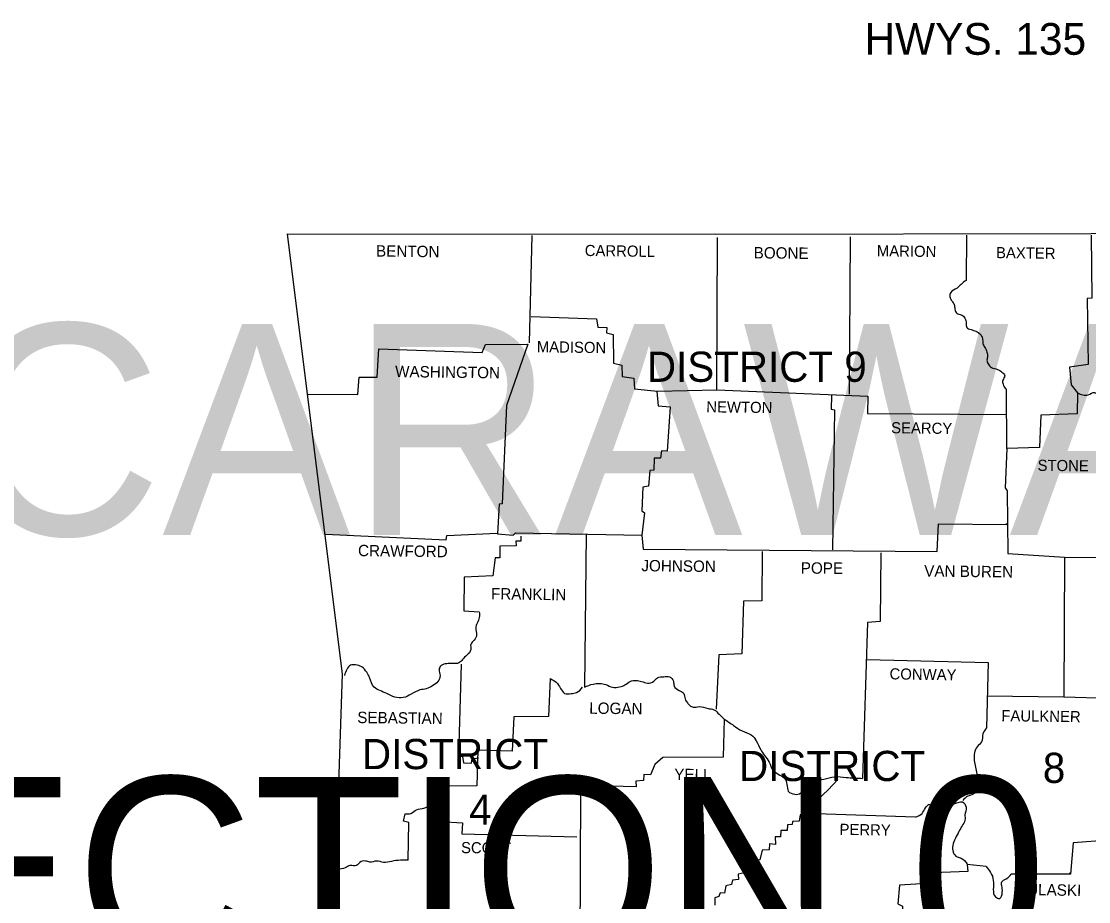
# Model space of a CAD drawing. Extents: x 166 to 3995, y -61 to 2074.
# Drawn here: x 2605.5 to 2999.8, y 1709.8 to 2035 of the extents above; entities that cross this region are included whole.
import ezdxf

# ---------------------------------------------------------------- set-up
doc = ezdxf.new("R2010")
doc.units = 0
for name, color, linetype in [('1', 7, 'Continuous'), ('2', 7, 'Continuous'), ('3', 7, 'Continuous'), ('R_Border', 7, 'Continuous')]:
    doc.layers.add(name, color=color, linetype=linetype)

msp = doc.modelspace()

# ---------------------------------------------------------------- linework, layer by layer
at = {"layer": '1'}
for points in [[(2703.71, 1956.42), (2861.92, 1956.32), (3000.75, 1956.61), (3164.54, 1959.16), (3240.46, 1960.92)], [(2703.71, 1956.42), (2723.96, 1793.81), (2715.15, 1528.37)], [(2794.01, 1955.83), (2793.13, 1916.21)], [(2954.67, 1956.03), (2954.47, 1939.3)], [(3000.75, 1956.03), (3000.95, 1932.74), (2999.28, 1932.64), (2999.58, 1908.28), (2992.73, 1907.3), (2993.32, 1900.75), (2995.66, 1897.71), (2995.47, 1889.98), (2982.16, 1889.5), (2981.67, 1877.56), (2969.54, 1877.17), (2968.95, 1862.69), (2969.64, 1861.51), (2969.93, 1838.42), (2990.87, 1837.05), (2990.58, 1785.49), (3007.21, 1785), (3007.21, 1732.56), (2994.1, 1731.58), (2993.12, 1720.04), (2971.11, 1719.94)], [(2793.82, 1925.89), (2817.89, 1925.11), (2818.47, 1921.98), (2821.8, 1921.88), (2821.7, 1919.92), (2824.05, 1919.34), (2824.25, 1908.67), (2827.28, 1907.99), (2827.48, 1903.78), (2831.78, 1903.19), (2831.98, 1899.28), (2840.49, 1898.4), (2862.4, 1898.89), (2862.6, 1955.15)], [(2911.62, 1955.34), (2911.33, 1897.22)], [(2711.44, 1897.22), (2729.73, 1897.13), (2730.22, 1903.58), (2736.97, 1903.58), (2737.56, 1914.05), (2775.72, 1912.68), (2776.89, 1915.62), (2792.64, 1915.72), (2784.72, 1893.02), (2783.15, 1856.72), (2781.98, 1856.62), (2781.39, 1845.66), (2787.17, 1845.17), (2788.05, 1846.05), (2834.72, 1845.17), (2835.21, 1839.99)], [(2840.29, 1898.2), (2840.68, 1892.92), (2845.18, 1892.63), (2844.01, 1876.19), (2841.96, 1876.29), (2841.56, 1873.65), (2839.22, 1873.65), (2839.12, 1869.14), (2837.65, 1869.05), (2837.16, 1863.27), (2835.01, 1862.98), (2834.72, 1854.17), (2835.69, 1853.49), (2834.72, 1845.17)], [(2862.4, 1898.89), (2918.17, 1896.54), (2918.08, 1890.18), (2969.25, 1889.79)], [(2904.77, 1896.83), (2904.67, 1891.75), (2905.94, 1891.45), (2905.16, 1839.79)], [(2969.54, 1877.17), (2969.44, 1899.18)], [(2835.21, 1839.99), (2943.81, 1839.11), (2944.3, 1849.38), (2969.54, 1849.09)], [(2969.25, 1849.19), (2969.54, 1849.48)], [(2717.89, 1845.56), (2762.41, 1843.51), (2762.61, 1845.08), (2781.2, 1845.96)], [(2814.17, 1845.56), (2813.48, 1789.11)], [(2790, 1844.78), (2790, 1843.02), (2788.14, 1843.02), (2788.24, 1841.26), (2782.27, 1841.16), (2782.18, 1836.76), (2780.51, 1836.76), (2779.63, 1830.2), (2769.06, 1829.71), (2768.97, 1817.29), (2774.64, 1816.9)], [(2879.14, 1839.21), (2879.04, 1820.91), (2872.29, 1820.81), (2871.7, 1801.34), (2863.09, 1801.05), (2862.11, 1780.89)], [(2922.97, 1838.72), (2922.77, 1813.28), (2918.08, 1812.89), (2916.22, 1755.36)], [(2990.87, 1837.05), (3041.16, 1836.76), (3045.46, 1838.81), (3045.17, 1800.56), (3042.24, 1799.29), (3039.59, 1797.04), (3038.71, 1796.16), (3038.62, 1785.2), (3006.62, 1785.2)], [(2917.88, 1799.29), (2962.59, 1798.21), (2962.01, 1774.04)], [(2767.99, 1797.53), (2767.01, 1763.87), (2768.48, 1763.48), (2768.77, 1761.13), (2771.71, 1760.93), (2772, 1762.6), (2774.35, 1762.99)], [(2800.86, 1792.24), (2800.18, 1778.25), (2787.46, 1778.15), (2786.77, 1765.43), (2774.15, 1765.73), (2773.76, 1752.62), (2760.55, 1752.52), (2760.16, 1739.41), (2768.48, 1738.92), (2768.18, 1734.91), (2810.65, 1733.73)], [(2962.1, 1785.88), (2990.58, 1785.49)], [(2865.14, 1777.27), (2864.75, 1763.18), (2842.45, 1763.09), (2839.51, 1760.54), (2837.85, 1756.63), (2835.4, 1756.82), (2835.3, 1754.57), (2832.47, 1754.28), (2832.56, 1752.22), (2818.38, 1752.62), (2817.89, 1751.05), (2812.02, 1750.86), (2811.82, 1693.62)], [(2907.12, 1754.96), (2903.6, 1751.15), (2899.78, 1747.53), (2895.38, 1746.84), (2895.38, 1742.25), (2893.22, 1741.95), (2892.83, 1739.6), (2890.39, 1739.41), (2890.19, 1738.33), (2888.53, 1738.23), (2888.43, 1736.18), (2886.08, 1736.08), (2885.89, 1733.73), (2883.93, 1733.73), (2884.03, 1730.99), (2881.88, 1731.19), (2881.78, 1729.04), (2879.14, 1728.84), (2878.35, 1725.32), (2875.03, 1725.03), (2874.73, 1723.07), (2872.97, 1722.58), (2872.48, 1720.52), (2870.23, 1720.04), (2870.43, 1717.98), (2868.18, 1717.78), (2867.79, 1716.22), (2865.73, 1715.63), (2865.24, 1712.99), (2863.68, 1713.09), (2863.19, 1711.72), (2861.72, 1711.23), (2861.62, 1708.59)], [(2748.32, 1725.22), (2748.62, 1739.02), (2746.66, 1739.6), (2747.25, 1742.25)], [(2935.79, 1741.07), (2895.47, 1742.34)], [(2961.91, 1722.77), (2954.86, 1723.56), (2955.16, 1720.92), (2942.34, 1720.43), (2941.95, 1716.61), (2929.91, 1715.93), (2929.23, 1709.08), (2930.99, 1708.2), (2930.99, 1703.7)], [(2992.63, 1720.13), (2993.12, 1720.62)]]:
    msp.add_lwpolyline(points, dxfattribs=at)
for points in [[(2954.47, 1939.3), (2952.71, 1937.83), (2951.15, 1936.46), (2948.8, 1934.8), (2948.5, 1933.23), (2949.29, 1931.66), (2950.07, 1930.39), (2950.36, 1928.63), (2951.05, 1927.16), (2952.71, 1926.58), (2954.08, 1925.31), (2954.57, 1923.54), (2954.77, 1921.88), (2956.33, 1921.1), (2958.09, 1920.51), (2959.76, 1919.34), (2960.54, 1917.87), (2960.73, 1916.01), (2961.42, 1914.54), (2962.2, 1912.78), (2962.4, 1911.31), (2962.2, 1909.85), (2962.59, 1908.48), (2963.87, 1907.11), (2966.12, 1906.42), (2967.68, 1905.44), (2968.76, 1904.07), (2968.07, 1902.41), (2968.17, 1900.94), (2969.05, 1899.18)], [(2995.66, 1897.71), (2999.58, 1897.03), (3001.93, 1897.91), (3003.59, 1895.37), (3004.47, 1893.41), (3005.94, 1890.57), (3008.29, 1889.69), (3010.05, 1888.13), (3010.05, 1886.46), (3008.48, 1884.9), (3007.31, 1883.33), (3007.7, 1881.47), (3008.09, 1878.93), (3008.09, 1876.48), (3007.5, 1874.23), (3007.01, 1872.18), (3007.5, 1870.42), (3009.36, 1870.71), (3011.32, 1872.18), (3013.37, 1872.18), (3015.33, 1871.1), (3017.38, 1869.24), (3019.44, 1869.63), (3021.1, 1870.12), (3023.45, 1870.81), (3025.11, 1869.93), (3026.58, 1868.75), (3028.34, 1866.89), (3030.01, 1865.72), (3032.16, 1864.64), (3034.8, 1863.96), (3037.25, 1862.3), (3037.64, 1859.46), (3037.54, 1857.01), (3037.34, 1853.98), (3037.15, 1850.65), (3037.44, 1847.42), (3038.52, 1845.27), (3039.89, 1842.73), (3040.28, 1840.38), (3040.18, 1836.66)], [(2774.64, 1816.9), (2774.64, 1814.84), (2773.86, 1812.69), (2773.37, 1810.83), (2773.66, 1808.39), (2772.78, 1806.43), (2771.51, 1804.86), (2771.51, 1802.91), (2770.04, 1800.85), (2768.48, 1799.29), (2767.11, 1798.01), (2764.66, 1797.82), (2762.61, 1797.72), (2760.55, 1797.04), (2759.77, 1795.57), (2760.16, 1793.32), (2759.38, 1791.17), (2757.32, 1789.5), (2755.07, 1788.43), (2752.73, 1788.03), (2749.5, 1786.47), (2746.56, 1785.2), (2743.43, 1785.39), (2740.5, 1786.66), (2737.85, 1787.84), (2735.8, 1789.01), (2734.14, 1792.63), (2733.06, 1794.59), (2731.2, 1796.55), (2728.95, 1797.33), (2727.09, 1797.13), (2724.84, 1793.32)], [(2800.86, 1792.24), (2803.02, 1790.87), (2804.68, 1788.62), (2806.15, 1786.76), (2808.59, 1786.66), (2810.55, 1787.06), (2812.8, 1789.01)], [(2813.48, 1789.11), (2816.71, 1790.19), (2819.06, 1790.38), (2821.41, 1789.99), (2823.86, 1789.01), (2826.5, 1789.21), (2828.45, 1789.89), (2830.41, 1791.17), (2832.56, 1791.56), (2834.62, 1791.17), (2836.77, 1790.58), (2839.12, 1791.26), (2840.49, 1792.54), (2842.84, 1792.93), (2844.89, 1792.93), (2846.36, 1791.26), (2846.65, 1789.5), (2848.51, 1787.84), (2850.17, 1786.76), (2850.66, 1784.71), (2851.54, 1783.24), (2852.43, 1782.26), (2853.7, 1781.67), (2855.85, 1781.87), (2859.18, 1781.19), (2861.33, 1780.7), (2863.29, 1779.03), (2865.14, 1777.27)], [(2865.14, 1777.27), (2868.57, 1774.92), (2871.8, 1772.87), (2875.12, 1771.4), (2876.98, 1769.25), (2878.65, 1765.92), (2880.02, 1763.87), (2881.78, 1761.32), (2883.05, 1758.49), (2885.1, 1756.92), (2887.26, 1755.55), (2888.33, 1753.11), (2888.82, 1750.66), (2891.17, 1749.49), (2893.42, 1749.97), (2894.69, 1751.44), (2895.87, 1753.99), (2898.51, 1754.77), (2901.93, 1755.06), (2905.85, 1755.94), (2910.15, 1755.75), (2916.22, 1755.36)], [(2962.01, 1774.04), (2960.73, 1771.79), (2960.15, 1768.86), (2958.58, 1767), (2957.6, 1764.85), (2957.51, 1762.01), (2958, 1759.47), (2958.48, 1757.02), (2958.88, 1754.77), (2958.39, 1751.93), (2957.11, 1749.49), (2955.16, 1748.8), (2953.3, 1747.14)], [(2747.25, 1742.25), (2749.4, 1742.44), (2751.45, 1743.81), (2754.19, 1744.4), (2756.93, 1745.87), (2760.36, 1747.43)], [(2935.79, 1741.07), (2938.23, 1742.44), (2939.5, 1744.5), (2941.07, 1745.77), (2942.63, 1744.01), (2944, 1741.46), (2945.47, 1741.46), (2947.33, 1743.22), (2948.5, 1744.79), (2949.97, 1745.96), (2951.54, 1746.45), (2953.2, 1746.65), (2954.47, 1744.79), (2954.08, 1741.85), (2954.08, 1739.9), (2953.01, 1737.84), (2951.83, 1735.69), (2950.56, 1733.24), (2949.58, 1730.6), (2949.78, 1728.06), (2951.15, 1726.39), (2952.71, 1725.91), (2954.86, 1723.75)], [(2748.32, 1725.22), (2745.49, 1725.12), (2742.26, 1724.73), (2739.32, 1724.34), (2736.68, 1724.83), (2734.23, 1724.44), (2732.57, 1724.83), (2730.52, 1724.34), (2729.34, 1723.17), (2726.9, 1723.17), (2725.13, 1722.38), (2722.3, 1721.7)], [(2961.91, 1722.77), (2963.57, 1720.62), (2964.55, 1717.69), (2964.55, 1714.36), (2965.33, 1711.62), (2966.9, 1711.03), (2967.88, 1713.38), (2967.68, 1715.73), (2967.68, 1717.1), (2969.34, 1718.27), (2971.11, 1719.94)]]:
    msp.add_spline(points, degree=3, dxfattribs=at)

# ---------------------------------------------------------------- texts
at = {"layer": '2'}
for s, height, rotation, p in [('BENTON', 4.207, 359.2527, (2736.48, 1948.1)), ('CARROLL', 4.109, 359.1481, (2813.58, 1948.3)), ('MARION', 4.109, 359.1854, (2921.5, 1948.2)), ('BOONE', 4.207, 359.4001, (2876, 1947.42)), ('BAXTER', 4.109, 359.2559, (2965.53, 1947.51)), ('MADISON', 4.109, 359.0906, (2795.87, 1912.78)), ('WASHINGTON', 4.206, 359.232, (2743.53, 1903.58)), ('NEWTON', 4.109, 359.2717, (2858.49, 1890.57)), ('SEARCY', 4.108, 359.2527, (2926.78, 1882.84)), ('STONE', 4.108, 359.4001, (2980.89, 1868.95)), ('CRAWFORD', 4.206, 359.2771, (2729.83, 1837.44)), ('JOHNSON', 4.207, 359.3514, (2834.52, 1831.87)), ('POPE', 4.207, 359.6155, (2893.42, 1830.99)), ('VAN BUREN', 4.207, 359.3508, (2939.01, 1829.91)), ('FRANKLIN', 4.207, 359.1815, (2778.95, 1821.5)), ('CONWAY', 4.108, 359.0371, (2926.2, 1791.95)), ('LOGAN', 4.207, 359.3969, (2815.25, 1779.23)), ('SEBASTIAN', 4.206, 359.2816, (2729.54, 1775.8)), ('FAULKNER', 4.109, 359.2486, (2967.49, 1776.49)), ('YELL', 4.207, 359.1987, (2846.65, 1754.77)), ('PERRY', 4.109, 359.0858, (2907.71, 1734.52)), ('SCOTT', 4.109, 359.4063, (2767.89, 1727.76)), ('PULASKI', 4.207, 359.053, (2973.26, 1712.31))]:
    msp.add_text(s, height=height, rotation=rotation, dxfattribs=at).set_placement(p)
for s, height, p in [('HWYS. 135 & 139 STRS.  & APPRS. (CARAWAY) (S)', 78, (796.83, 1845.2)), ('ROUTE 135 SECTION 2 & ROUTE 139 SECTION 0', 68, (872.06, 1687.93))]:
    msp.add_text(s, height=height, dxfattribs=at).set_placement(p)
at = {"layer": '3'}
for s, height, p in [('DISTRICT 9', 11.154, (2836.57, 1901.82)), ('DISTRICT', 11.154, (2731.3, 1758.78)), ('DISTRICT', 11.154, (2870.62, 1754.38)), ('8', 11.15, (2982.85, 1753.69)), ('4', 11.15, (2770.92, 1738.23))]:
    msp.add_text(s, height=height, dxfattribs=at).set_placement(p)
at = {"layer": 'R_Border'}
msp.add_text('HWYS. 135 & 139 STRS. & APPRS. (CARAWAY) (S)', height=11.724, dxfattribs=at).set_placement((2916.93, 2022.61))

doc.saveas('drawing.dxf')
